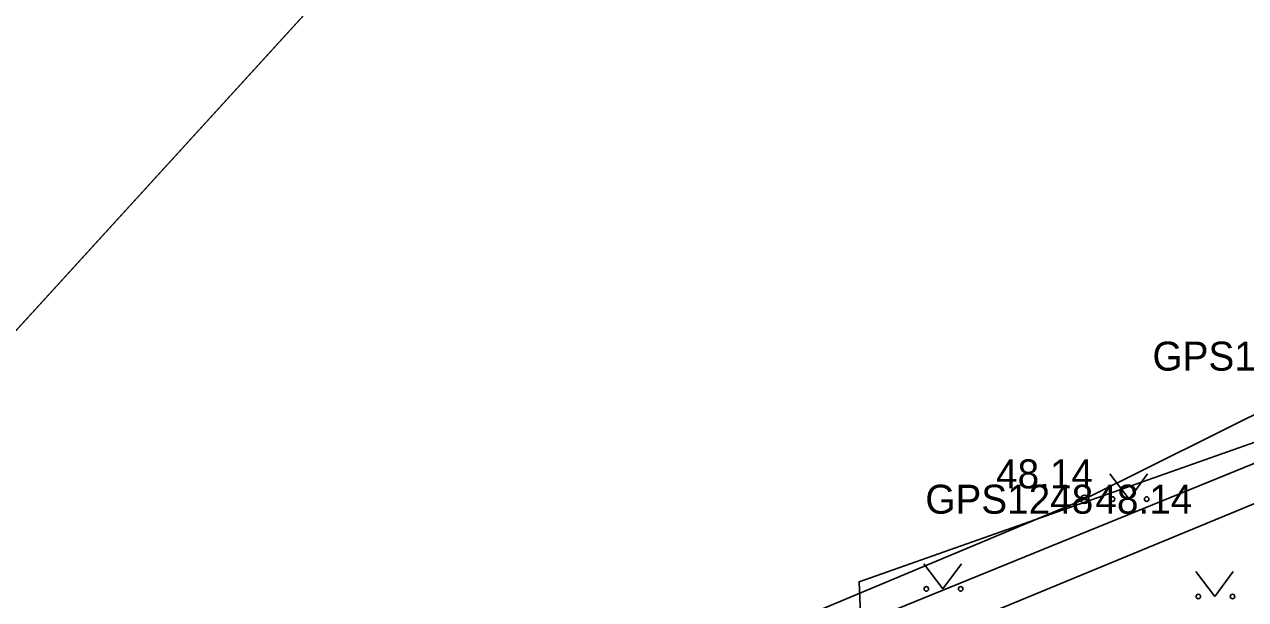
# Model space of a CAD drawing. Extents: x 551623 to 559850, y 6561220 to 6567135.
# Drawn here: x 556854.79 to 556884.3, y 6565278.16 to 6565292.04 of the extents above; entities that cross this region are included whole.
import ezdxf

# ---------------------------------------------------------------- set-up
doc = ezdxf.new("R2010")
doc.units = 0
for name, color, linetype in [('HALJASTUS', 7, 'Continuous'), ('KORGUS-EH2000', 7, 'Continuous'), ('KTRASS', 7, 'Continuous'), ('MOOTKORG-EH2000', 7, 'Continuous'), ('MOOTMPUNKT', 7, 'Continuous'), ('MOOTNR', 7, 'Continuous'), ('MOOTPIIR', 7, 'Continuous'), ('PIIR', 7, 'Continuous'), ('VTRASS', 7, 'Continuous')]:
    doc.layers.add(name, color=color, linetype=linetype)

msp = doc.modelspace()

# ---------------------------------------------------------------- linework, layer by layer
at = {"layer": 'HALJASTUS'}
for p, q in [((556881.022, 6565281.188), (556881.486, 6565280.581)), ((556881.486, 6565280.581), (556881.931, 6565281.188)), ((556876.525, 6565279.019), (556876.989, 6565278.412)), ((556876.989, 6565278.412), (556877.434, 6565279.019)), ((556883.098, 6565278.834), (556883.562, 6565278.228)), ((556883.562, 6565278.228), (556884.007, 6565278.834))]:
    msp.add_line(p, q, dxfattribs=at)
for centre in [(556881.085, 6565280.581), (556881.913, 6565280.581), (556876.588, 6565278.412), (556877.417, 6565278.412), (556883.161, 6565278.228), (556883.989, 6565278.228)]:
    msp.add_circle(centre, 0.055, dxfattribs=at)
at = {"layer": 'KORGUS-EH2000'}
msp.add_circle((556880.413, 6565280.578), 0.1, dxfattribs=at)
at = {"layer": 'KTRASS'}
msp.add_lwpolyline([(556865.402, 6565254.032), (556871.396, 6565275.058), (556892.504, 6565283.769), (556915.486, 6565293.126), (556926.41, 6565297.925), (556943.376, 6565309.264), (556953.177, 6565321.905), (556974.878, 6565343.903), (556994.604, 6565358.984), (557007.739, 6565364.827)], dxfattribs=at)
at = {"layer": 'MOOTMPUNKT'}
msp.add_circle((556880.413, 6565280.578), 0.1, dxfattribs=at)
at = {"layer": 'MOOTPIIR'}
msp.add_lwpolyline([(556926.19, 6565300.04), (556918.779, 6565296.992), (556900.373, 6565288.625), (556891.588, 6565286.132), (556880.413, 6565280.578), (556871.115, 6565276.693), (556861.98, 6565273.359), (556854.509, 6565270.787), (556847.039, 6565268.611), (556845.54, 6565266.65), (556845.851, 6565260.393), (556817.364, 6565249.633), (556799.911, 6565243.207), (556776.314, 6565234.412), (556752.299, 6565224.302), (556722.286, 6565214.456)], dxfattribs=at)
at = {"layer": 'PIIR'}
for points in [[(556591.74, 6565273.2), (556611.32, 6565356.67), (556613.56, 6565366.23), (556615.14, 6565380.2), (556960.95, 6565401.08), (556937.33, 6565375.23), (556904.84, 6565339.67), (556845.15, 6565274.33), (556845.54, 6565266.65), (556846.17, 6565253.94), (556847.95, 6565219.09), (556848.22, 6565213.26)], [(556904.84, 6565339.67), (556926.94, 6565298.71), (556856.85, 6565270.19), (556855.29, 6565270.63), (556845.54, 6565266.65), (556845.15, 6565274.33)]]:
    msp.add_lwpolyline(points, close=True, dxfattribs=at)
msp.add_lwpolyline([(556933.08, 6565290.38), (556916.13, 6565283.47), (556880.91, 6565269.21), (556860.96, 6565261.06), (556860.15, 6565259.65), (556846.17, 6565253.94), (556845.54, 6565266.65), (556855.29, 6565270.63), (556856.85, 6565270.19), (556926.94, 6565298.71)], dxfattribs=at)
at = {"layer": 'VTRASS'}
msp.add_lwpolyline([(557036.652, 6565383.055), (557029.612, 6565366.205), (557027.956, 6565364.898), (557020.892, 6565360.985), (557004.502, 6565358.325), (556993.402, 6565354.055), (556977.512, 6565341.735), (556958.552, 6565323.805), (556949.092, 6565312.965), (556941.832, 6565305.455), (556936.372, 6565301.775), (556930.872, 6565299.495), (556913.102, 6565292.365), (556898.112, 6565286.745), (556874.962, 6565278.585), (556875.38, 6565268.285), (556875.842, 6565263.753)], dxfattribs=at)

# ---------------------------------------------------------------- texts
at = {"layer": 'KORGUS-EH2000'}
msp.add_text(' 48.14', height=0.7, dxfattribs=at).set_placement((556878.012, 6565280.84))
at = {"layer": 'MOOTKORG-EH2000'}
msp.add_text(' 48.14', height=0.7, dxfattribs=at).set_placement((556880.413, 6565280.228))
at = {"layer": 'MOOTNR'}
for s, p in [('GPS1249 ', (556882.053, 6565283.683)), ('GPS1248 ', (556876.563, 6565280.228))]:
    msp.add_text(s, height=0.7, dxfattribs=at).set_placement(p)

doc.saveas('drawing.dxf')
